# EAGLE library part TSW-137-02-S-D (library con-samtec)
THROUGH-HOLE .025" SQ POST HEADER Source: Samtec TSW.pdf
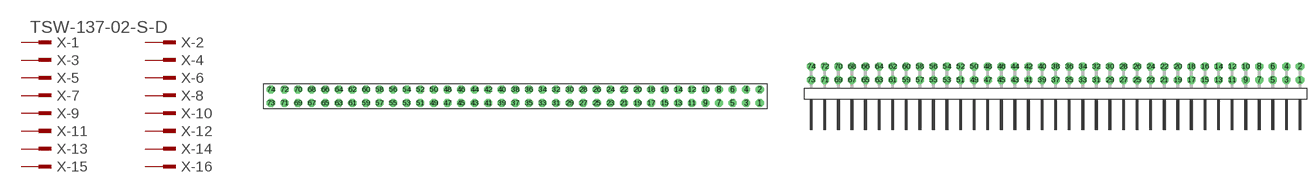
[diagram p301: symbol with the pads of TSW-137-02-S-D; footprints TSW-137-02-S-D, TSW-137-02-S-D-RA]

Designator prefix X; gates -1=MPINV -2=MPIN -3=MPIN -4=MPIN -5=MPIN -6=MPIN -7=MPIN -8=MPIN -9=MPIN -10=MPIN -11=MPIN -12=MPIN -13=MPIN -14=MPIN -15=MPIN -16=MPIN -17=MPIN -18=MPIN -19=MPIN -20=MPIN -21=MPIN -22=MPIN -23=MPIN -24=MPIN -25=MPIN -26=MPIN -27=MPIN -28=MPIN -29=MPIN -30=MPIN -31=MPIN -32=MPIN -33=MPIN -34=MPIN -35=MPIN -36=MPIN -37=MPIN -38=MPIN -39=MPIN -40=MPIN -41=MPIN -42=MPIN -43=MPIN -44=MPIN -45=MPIN -46=MPIN -47=MPIN -48=MPIN -49=MPIN -50=MPIN -51=MPIN -52=MPIN -53=MPIN -54=MPIN -55=MPIN -56=MPIN -57=MPIN -58=MPIN -59=MPIN -60=MPIN -61=MPIN -62=MPIN -63=MPIN -64=MPIN -65=MPIN -66=MPIN -67=MPIN -68=MPIN -69=MPIN -70=MPIN -71=MPIN -72=MPIN -73=MPIN -74=MPIN

## TSW-137-02-S-D (OC_FARNELL: unknown; OC_NEWARK: unknown)  [TSW-137-02-S-D]
1  -1:1  pas
2  -2:1  pas
3  -3:1  pas
4  -4:1  pas
5  -5:1  pas
6  -6:1  pas
7  -7:1  pas
8  -8:1  pas
9  -9:1  pas
10  -10:1  pas
11  -11:1  pas
12  -12:1  pas
13  -13:1  pas
14  -14:1  pas
15  -15:1  pas
16  -16:1  pas
17  -17:1  pas
18  -18:1  pas
19  -19:1  pas
20  -20:1  pas
21  -21:1  pas
22  -22:1  pas
23  -23:1  pas
24  -24:1  pas
25  -25:1  pas
26  -26:1  pas
27  -27:1  pas
28  -28:1  pas
29  -29:1  pas
30  -30:1  pas
31  -31:1  pas
32  -32:1  pas
33  -33:1  pas
34  -34:1  pas
35  -35:1  pas
36  -36:1  pas
37  -37:1  pas
38  -38:1  pas
39  -39:1  pas
40  -40:1  pas
41  -41:1  pas
42  -42:1  pas
43  -43:1  pas
44  -44:1  pas
45  -45:1  pas
46  -46:1  pas
47  -47:1  pas
48  -48:1  pas
49  -49:1  pas
50  -50:1  pas
51  -51:1  pas
52  -52:1  pas
53  -53:1  pas
54  -54:1  pas
55  -55:1  pas
56  -56:1  pas
57  -57:1  pas
58  -58:1  pas
59  -59:1  pas
60  -60:1  pas
61  -61:1  pas
62  -62:1  pas
63  -63:1  pas
64  -64:1  pas
65  -65:1  pas
66  -66:1  pas
67  -67:1  pas
68  -68:1  pas
69  -69:1  pas
70  -70:1  pas
71  -71:1  pas
72  -72:1  pas
73  -73:1  pas
74  -74:1  pas

## TSW-137-02-S-D-RA (OC_FARNELL: unknown; OC_NEWARK: unknown)  [TSW-137-02-S-D-RA]
Pads as for TSW-137-02-S-D

## Footprint TSW-137-02-S-D (pad centres in mm)
THROUGH-HOLE .025" SQ POST HEADER Source: Samtec TSW.pdf
drill 1 pad 1.5 octagon: 1 45.72,-1.27; 2 45.72,1.27; 3 43.18,-1.27; 4 43.18,1.27; 5 40.64,-1.27; 6 40.64,1.27; 7 38.1,-1.27; 8 38.1,1.27; 9 35.56,-1.27; 10 35.56,1.27; 11 33.02,-1.27; 12 33.02,1.27; 13 30.48,-1.27; 14 30.48,1.27; 15 27.94,-1.27; 16 27.94,1.27; 17 25.4,-1.27; 18 25.4,1.27; 19 22.86,-1.27; 20 22.86,1.27; 21 20.32,-1.27; 22 20.32,1.27; 23 17.78,-1.27; 24 17.78,1.27; 25 15.24,-1.27; 26 15.24,1.27; 27 12.7,-1.27; 28 12.7,1.27; 29 10.16,-1.27; 30 10.16,1.27; 31 7.62,-1.27; 32 7.62,1.27; 33 5.08,-1.27; 34 5.08,1.27; 35 2.54,-1.27; 36 2.54,1.27; 37 0,-1.27; 38 0,1.27; 39 -2.54,-1.27; 40 -2.54,1.27; 41 -5.08,-1.27; 42 -5.08,1.27; 43 -7.62,-1.27; 44 -7.62,1.27; 45 -10.16,-1.27; 46 -10.16,1.27; 47 -12.7,-1.27; 48 -12.7,1.27; 49 -15.24,-1.27; 50 -15.24,1.27; 51 -17.78,-1.27; 52 -17.78,1.27; 53 -20.32,-1.27; 54 -20.32,1.27; 55 -22.86,-1.27; 56 -22.86,1.27; 57 -25.4,-1.27; 58 -25.4,1.27; 59 -27.94,-1.27; 60 -27.94,1.27; 61 -30.48,-1.27; 62 -30.48,1.27; 63 -33.02,-1.27; 64 -33.02,1.27; 65 -35.56,-1.27; 66 -35.56,1.27; 67 -38.1,-1.27; 68 -38.1,1.27; 69 -40.64,-1.27; 70 -40.64,1.27; 71 -43.18,-1.27; 72 -43.18,1.27; 73 -45.72,-1.27; 74 -45.72,1.27

## Footprint TSW-137-02-S-D-RA (pad centres in mm)
THROUGH-HOLE .025" SQ POST HEADER Source: Samtec TSW.pdf
drill 1 pad 1.5 octagon: 1 45.72,1.524; 2 45.72,4.064; 3 43.18,1.524; 4 43.18,4.064; 5 40.64,1.524; 6 40.64,4.064; 7 38.1,1.524; 8 38.1,4.064; 9 35.56,1.524; 10 35.56,4.064; 11 33.02,1.524; 12 33.02,4.064; 13 30.48,1.524; 14 30.48,4.064; 15 27.94,1.524; 16 27.94,4.064; 17 25.4,1.524; 18 25.4,4.064; 19 22.86,1.524; 20 22.86,4.064; 21 20.32,1.524; 22 20.32,4.064; 23 17.78,1.524; 24 17.78,4.064; 25 15.24,1.524; 26 15.24,4.064; 27 12.7,1.524; 28 12.7,4.064; 29 10.16,1.524; 30 10.16,4.064; 31 7.62,1.524; 32 7.62,4.064; 33 5.08,1.524; 34 5.08,4.064; 35 2.54,1.524; 36 2.54,4.064; 37 0,1.524; 38 0,4.064; 39 -2.54,1.524; 40 -2.54,4.064; 41 -5.08,1.524; 42 -5.08,4.064; 43 -7.62,1.524; 44 -7.62,4.064; 45 -10.16,1.524; 46 -10.16,4.064; 47 -12.7,1.524; 48 -12.7,4.064; 49 -15.24,1.524; 50 -15.24,4.064; 51 -17.78,1.524; 52 -17.78,4.064; 53 -20.32,1.524; 54 -20.32,4.064; 55 -22.86,1.524; 56 -22.86,4.064; 57 -25.4,1.524; 58 -25.4,4.064; 59 -27.94,1.524; 60 -27.94,4.064; 61 -30.48,1.524; 62 -30.48,4.064; 63 -33.02,1.524; 64 -33.02,4.064; 65 -35.56,1.524; 66 -35.56,4.064; 67 -38.1,1.524; 68 -38.1,4.064; 69 -40.64,1.524; 70 -40.64,4.064; 71 -43.18,1.524; 72 -43.18,4.064; 73 -45.72,1.524; 74 -45.72,4.064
